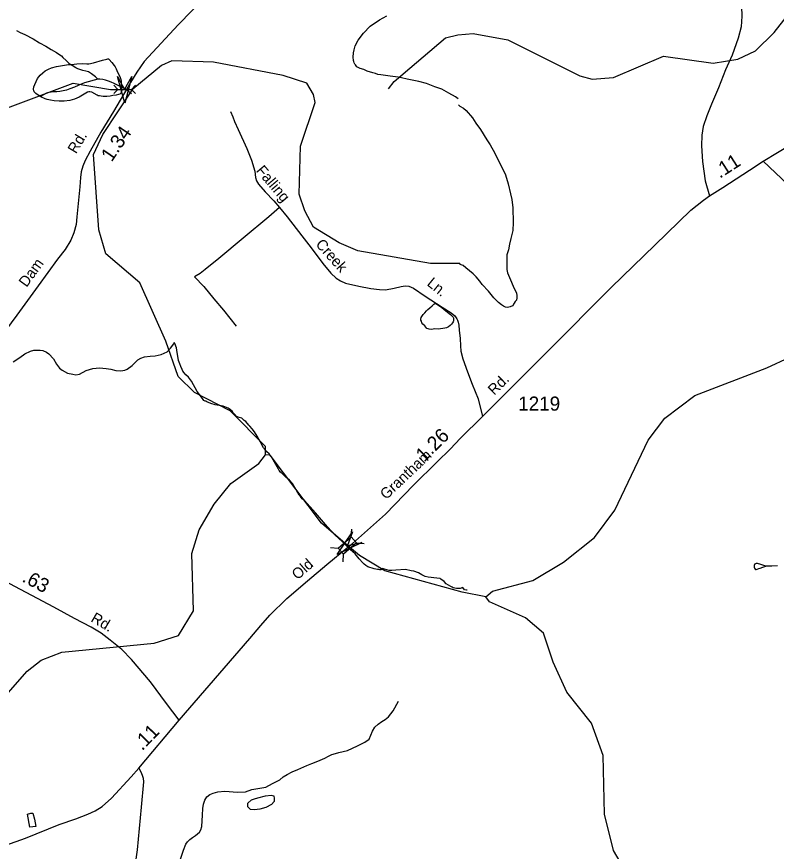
# Model space of a CAD drawing. Extents: x 2206922 to 2357709, y 510027 to 673830.
# Drawn here: x 2257136 to 2263859, y 570736 to 578126 of the extents above; entities that cross this region are included whole.
import ezdxf

# ---------------------------------------------------------------- set-up
doc = ezdxf.new("R2010")
doc.units = 0
for name, color, linetype in [('Exist Hydrographic Creek Single Shore', 7, 'Continuous'), ('Exist Hydrographic Misc Water Feature', 7, 'Continuous'), ('Exist Road Non-System Type 51', 7, 'Continuous'), ('Exist Road Non-System Type 51 Label', 7, 'Continuous'), ('Exist Road Secondary Mileage Hundredths English Label', 7, 'Continuous'), ('Exist Road Secondary Structure Pipe CELL', 7, 'Continuous'), ('Exist Road Secondary Structure Standard Bridge Attributed CELL', 7, 'Continuous'), ('Exist Road Secondary Structure Standard Bridge CELL', 7, 'Continuous'), ('Exist Road Secondary Type 51 Attributed', 7, 'Continuous'), ('Exist Road Secondary Type 51 Label', 7, 'Continuous'), ('Exist Road Secondary Type 51 Number Label', 7, 'Continuous')]:
    doc.layers.add(name, color=color, linetype=linetype)

msp = doc.modelspace()

# ---------------------------------------------------------------- linework, layer by layer
at = {"layer": 'Exist Hydrographic Creek Single Shore'}
for points in [[(2260540.9, 577584), (2260511, 577589.8), (2260442.7, 577599.2), (2260359.2, 577610.2), (2260333, 577614.1), (2260311.1, 577621.9), (2260287.3, 577629.6), (2260236.8, 577643.3), (2260208.9, 577657.2), (2260177, 577666.9), (2260146.4, 577682.5), (2260134.5, 577700.5), (2260128.1, 577706.3), (2260122.2, 577718.6), (2260118.3, 577728.5), (2260117.9, 577738.2), (2260114, 577766.4), (2260117.7, 577806.4), (2260123.2, 577832.3), (2260131, 577868.5), (2260156.9, 577918.5), (2260204.2, 577981.1), (2260265.5, 578043.3), (2260346.9, 578097.9), (2260413, 578134.6)], [(2261058.5, 575940.7), (2260798.5, 575941.1), (2260155.4, 576052.5), (2259988.5, 576124.8), (2259762.5, 576263.8), (2259686.5, 576406.4), (2259635.4, 576555), (2259648.5, 576981.1), (2259778.5, 577365.5), (2259761.5, 577437.9), (2259702.5, 577537.6), (2259493.5, 577604.1), (2258876.5, 577724.8), (2258509.5, 577735.5), (2258418.4, 577694.7), (2258163, 577484)], [(2261044.1, 577399.9), (2261018.5, 577416), (2260960.3, 577449.5), (2260899.8, 577485), (2260835.8, 577506.3), (2260763.4, 577533.9), (2260695.3, 577551), (2260591.4, 577572.4), (2260540.9, 577584)], [(2252747.3, 576540.1), (2252846.3, 576623.4), (2253510.3, 576937.9), (2253851.3, 576973.7), (2254770.3, 576682.9), (2255195.4, 576644.8), (2255603.5, 576662.8), (2256002.5, 576766.2), (2256359.5, 576913.1), (2257030.4, 577309.5), (2257636.4, 577536.7), (2257964.7, 577482.8), (2258091.2, 577482.8), (2258163, 577484)], [(2259337.5, 574245.5), (2259337.5, 574321.1), (2259026.4, 574635.6), (2258708.4, 574799.4), (2258565.4, 574940.1), (2258454.5, 575253.9), (2258225.5, 575770.1), (2257923.4, 576025.5), (2257863.3, 576239.9), (2257816.4, 576906.7), (2257898.4, 577082.1), (2258163, 577484)], [(2261044.7, 577344.3), (2261056.6, 577334.3), (2261089, 577316.5), (2261113.4, 577294.6), (2261170, 577229.3), (2261198.9, 577183.2), (2261241.6, 577127.6), (2261298.2, 577036.4), (2261326.7, 576990.7), (2261369.1, 576919), (2261461.2, 576726), (2261485.8, 576646.4), (2261506.9, 576556.4), (2261519, 576508.8), (2261525.8, 576432.7), (2261526.2, 576388.8), (2261530.7, 576346.8), (2261529.3, 576304.9), (2261525.8, 576232.8), (2261508.1, 576162.9), (2261496.9, 576110.6), (2261489.3, 576062.7), (2261473.9, 576018.4), (2261474.5, 575976.5), (2261474.9, 575922.6), (2261473.1, 575886.7), (2261481.3, 575856.7), (2261496.1, 575816.8), (2261514.1, 575775.1), (2261536.4, 575725.1), (2261558.8, 575681.6), (2261563.1, 575653.4), (2261563.1, 575635.5), (2261559.2, 575617.4), (2261547.5, 575605.4), (2261537.7, 575589.5), (2261531.7, 575579.4), (2261525.8, 575567.4), (2261510, 575561.2), (2261504, 575556.8), (2261492, 575555), (2261478, 575552.6), (2261462, 575554.6), (2261443.8, 575562.3), (2261425.9, 575574.3), (2261399.9, 575594), (2261359.5, 575635.8), (2261310.7, 575695.1), (2261256.6, 575754.7), (2261235.8, 575784.2), (2261203.4, 575821.9), (2261175.3, 575849.7), (2261142.7, 575875.7), (2261110.3, 575903.3), (2261088.2, 575923.2), (2261062.2, 575932.9), (2261058.5, 575940.7)], [(2261288.5, 572989.3), (2261079.6, 573029.6), (2260395.5, 573220.6), (2260170.3, 573354.4), (2260063.4, 573443.3), (2259833.5, 573641.9), (2259379.5, 574244.7), (2259337.5, 574245.5)], [(2262561.5, 570444.8), (2262535.5, 570543.7), (2262417.6, 570742.9), (2262339.4, 571066), (2262326.5, 571584.4), (2262223.6, 571871.8), (2262004.6, 572145.1), (2261884.4, 572409.9), (2261799.5, 572667.5), (2261639.6, 572801.9), (2261321.6, 572946), (2261288.5, 572989.3)]]:
    msp.add_lwpolyline(points, dxfattribs=at)
at = {"layer": 'Exist Hydrographic Misc Water Feature'}
for points in [[(2261041.5, 577966.3), (2261174.5, 577976.8), (2261483.5, 577921.4), (2262119.4, 577603.5), (2262228.5, 577571.7), (2262419.4, 577587.6), (2262859.4, 577775.5), (2263301.5, 577714), (2263517.5, 577749), (2263674.5, 577824.5), (2263840.6, 577985.2), (2264086.5, 578304.9), (2264260.6, 578449), (2264766.4, 578642), (2264998.5, 578804.6), (2265576.6, 579301.3), (2265965.6, 579539.4), (2266381.6, 579675.3), (2266780.7, 579736), (2266980.6, 579722.2), (2267497.5, 579626.5), (2268096.5, 579657)], [(2257133.4, 578004), (2257167.8, 577986.3)], [(2257167.8, 577986.3), (2257207.6, 577968.5), (2257282, 577929.4), (2257338, 577893.7), (2257392.5, 577866), (2257440.7, 577834.4), (2257488.9, 577808.9), (2257518.7, 577789), (2257531.2, 577779.5), (2257543.3, 577765.5), (2257573.4, 577737.8), (2257597.6, 577713.9), (2257611.7, 577704.1)], [(2260427.5, 577486.8), (2260476.5, 577551.4), (2260931.5, 577939.1), (2261041.5, 577966.3)], [(2257350.1, 577417.8), (2257325.7, 577432), (2257306, 577445.6), (2257291.7, 577459.5), (2257287.8, 577469.4), (2257285.7, 577485.5), (2257287.4, 577505.6), (2257294.9, 577525.5), (2257307, 577553.7), (2257321, 577579.6), (2257342.7, 577607.9), (2257366.3, 577629.9), (2257388.2, 577646.1), (2257416.1, 577662.6), (2257444, 577674.6), (2257487.7, 577685), (2257541.8, 577695.5), (2257593.9, 577701.8), (2257611.7, 577704.1)], [(2257611.7, 577704.1), (2257621.4, 577704.2), (2257667.7, 577708.6), (2257719.4, 577710.9), (2257757.5, 577709.2), (2257775.4, 577709.4), (2257815.4, 577717.5), (2257895.3, 577740.3), (2257933.1, 577750.5), (2257941.1, 577752.5), (2257947, 577752.9), (2257950.9, 577750.6), (2257955.4, 577746.7), (2257979.2, 577719.2), (2257999.5, 577693), (2258007.9, 577681.2), (2258017.5, 577663.5), (2258027.8, 577635.6), (2258038.3, 577613.4), (2258050.4, 577587.6), (2258058.6, 577569.7), (2258060.6, 577559.7), (2258060.8, 577539.8), (2258061, 577515.9), (2258063.3, 577501.7)], [(2257854.7, 577574.1), (2257832.6, 577593.7), (2257798.1, 577619.6), (2257772.3, 577637.3), (2257748.1, 577644.9), (2257721.9, 577650.9), (2257678.2, 577664.4), (2257657.7, 577674.4), (2257625.7, 577694.2), (2257611.7, 577704.1)], [(2257854.7, 577574.1), (2257737, 577541.2), (2257706.9, 577528.7), (2257679, 577516.7), (2257647.4, 577502.4), (2257607.2, 577486.1), (2257575.5, 577475.9), (2257545.7, 577469.4), (2257517.4, 577465.2), (2257491.8, 577461), (2257459.8, 577460.9), (2257441.6, 577458.8), (2257429.7, 577456.5), (2257399.9, 577448.5), (2257378, 577436.4), (2257362.2, 577428.2), (2257350.1, 577417.8)], [(2258063.3, 577501.7), (2258041.1, 577513.6), (2257998.9, 577533.3), (2257970.6, 577546.9), (2257948.9, 577556.7), (2257922.6, 577564.7), (2257896.8, 577570.3), (2257870.7, 577572.2), (2257854.7, 577574.1)], [(2258063.3, 577501.7), (2258065.1, 577473.9), (2258061.4, 577459.8), (2258057.3, 577447.9), (2258047.9, 577441.6), (2258037.8, 577437.4), (2258015.5, 577431.5), (2257987.6, 577427.2), (2257961.8, 577422.9), (2257933.9, 577420.7), (2257915.6, 577418.6), (2257899.8, 577420.5), (2257883.6, 577422.6), (2257867.7, 577424.2), (2257857.8, 577426.1), (2257847.8, 577430), (2257799.8, 577457.5), (2257781.7, 577461.5), (2257773.7, 577459.4), (2257763.5, 577457.3), (2257688, 577412.7), (2257646.2, 577396.3), (2257606.4, 577384.1), (2257556.4, 577377.8), (2257510.5, 577377.5), (2257468.6, 577380.9), (2257434.4, 577386.9), (2257405.9, 577392.4), (2257386.4, 577400.2), (2257350.1, 577417.8)], [(2258153.3, 577442.4), (2258123.4, 577468.3), (2258077.2, 577496), (2258063.3, 577501.7)], [(2261288.5, 572989.3), (2261346.6, 573040.7), (2261703.6, 573135.1), (2261976.5, 573296.8), (2262249.6, 573514.3), (2262430.5, 573756.6), (2262724.5, 574377.2), (2262872.6, 574570.9), (2263137.5, 574772.2), (2263776.4, 575018.4), (2264182.4, 575206.9), (2264612.6, 575519.6), (2265102.5, 575706.5), (2265933.6, 575939), (2266231.5, 576051), (2266422.6, 576152.1), (2266901.6, 576604.8), (2267215.6, 576808.4)], [(2260841.3, 575589.4), (2260845.2, 575587.2), (2260899.8, 575551.8), (2260933.8, 575521.9), (2260974, 575490.3), (2260994.1, 575472.7), (2260999.8, 575466.6), (2261002.5, 575458.9), (2261002.5, 575448.7), (2261002.3, 575432.9), (2260998.4, 575424.6), (2260992.4, 575416.6), (2260982.8, 575404.6), (2260972.6, 575392.4), (2260958.8, 575380.3), (2260939.1, 575372.3), (2260924.8, 575368.4), (2260869, 575359.7), (2260834.8, 575361.3), (2260810.8, 575357.2), (2260787, 575359.2), (2260776.9, 575361.1), (2260767.1, 575365), (2260748.8, 575388.8), (2260730.6, 575404.5), (2260723, 575416.6), (2260718.5, 575430.3), (2260714.2, 575438.6), (2260714.2, 575448.4), (2260716, 575462.3), (2260722.2, 575470.3), (2260734.1, 575488.4), (2260748.2, 575504.5), (2260762, 575520.7), (2260775.9, 575532.8), (2260791.3, 575549.1), (2260813.4, 575567.3), (2260827.4, 575579.4), (2260837.2, 575587.2), (2260841.3, 575589.4)], [(2257105.5, 575069.4), (2257162.9, 575107.8), (2257208.6, 575139.9), (2257258.4, 575164.4), (2257288.4, 575172.8), (2257318.5, 575174.8), (2257344.6, 575172.9), (2257368.1, 575169.3), (2257398.5, 575155.4), (2257420.6, 575142), (2257461, 575096.1), (2257489.1, 575050.5), (2257513.7, 575014.8), (2257539.6, 574996.7), (2257585.9, 574971.1), (2257632, 574959.6), (2257657.7, 574955.7), (2257691.9, 574961.9), (2257749.7, 574992.6), (2257809.4, 575011.2), (2257869.5, 575015.5), (2257927.7, 575012), (2257969.2, 575006.1), (2258013.7, 574994.5), (2258057.7, 574989.1), (2258091.6, 574995.4), (2258113.5, 575005.5), (2258156.8, 575037.9), (2258208.7, 575088.5), (2258234.3, 575102.4), (2258266.5, 575114.6), (2258316.5, 575120.9), (2258360.2, 575123.6), (2258414.1, 575135.7), (2258468, 575158.4), (2258498, 575192.4), (2258525.3, 575228.9), (2258529.4, 575240.8)], [(2259383, 574236.2), (2259370.7, 574254.3), (2259350.6, 574273.9), (2259328.7, 574299.6), (2259320.4, 574309.7), (2259294, 574357.5), (2259263.9, 574411.1), (2259241.1, 574451.1), (2259221.2, 574476.7), (2259199.3, 574500.3), (2259189, 574510.4), (2259163, 574540.3), (2259150.5, 574550.2), (2259138.6, 574562.2), (2259128.7, 574571.8), (2259104.3, 574575.9), (2259090.4, 574581.6), (2259078.5, 574589.5), (2259070.3, 574599.3), (2259052, 574619.5), (2259042, 574633.1), (2259027.8, 574645), (2259015.9, 574652.9), (2259007.5, 574659), (2258963.7, 574676.6), (2258893.7, 574689.9), (2258855.4, 574701.8), (2258819.3, 574715.4), (2258809.3, 574721.3), (2258803.1, 574723.1), (2258793.1, 574729.1), (2258779.1, 574744.9), (2258734.4, 574808.5), (2258681.7, 574900.3), (2258657.7, 574934), (2258633.7, 574955.8), (2258619.4, 574971.8), (2258605.2, 574987.3), (2258599.1, 575003.6), (2258589, 575027.5), (2258580.6, 575051.4), (2258568.5, 575083.2), (2258553.8, 575173.1), (2258549.9, 575192.7), (2258535.3, 575231), (2258529.4, 575240.8)], [(2256998.4, 572069.2), (2257229.5, 572330.2), (2257353.4, 572429.4), (2257536.5, 572497.8), (2258351.4, 572579.7), (2258567.5, 572647.5), (2258699.6, 572864.6), (2258686.4, 573373.2), (2258751.4, 573581.8), (2258883.5, 573808.7), (2259031.5, 573992.7), (2259279.4, 574171.3), (2259337.5, 574245.5)], [(2260374.4, 573238.8), (2260367, 573232.6), (2260358.6, 573228.6), (2260348.8, 573228.5), (2260340.8, 573230.5), (2260328.7, 573230.3), (2260314.5, 573234.5), (2260298.5, 573238.1), (2260244.6, 573255.5), (2260224.5, 573267.5), (2260212, 573277.5), (2260198.3, 573289.3), (2260165.9, 573327), (2260131.6, 573368.7), (2260089, 573406.3), (2260016.8, 573477.7), (2259954.5, 573535.3), (2259885.8, 573610.5), (2259781, 573731.8), (2259684, 573840.9), (2259663.7, 573856.5), (2259647.9, 573876.3), (2259635.8, 573890.3), (2259623.3, 573910.4), (2259597.5, 573956.1), (2259576.6, 573992.1), (2259548.9, 574021.8), (2259518.7, 574047.5), (2259492.3, 574075), (2259471.8, 574093), (2259459.7, 574107), (2259454.1, 574118.9), (2259417.6, 574180.7), (2259393, 574224.2), (2259383, 574236.2)], [(2261083.7, 573072.3), (2261059.7, 573064.1), (2261029.6, 573064.2), (2261013.8, 573066.2), (2260999.6, 573070), (2260989.6, 573075.9), (2260979.5, 573081.9), (2260937.5, 573105.3), (2260919, 573125.5), (2260889.1, 573147), (2260882.9, 573150.8), (2260855.1, 573154.6), (2260779, 573162), (2260750.9, 573169.9), (2260722.6, 573183.5), (2260692.5, 573201.4), (2260650.4, 573217.1), (2260628.5, 573220.8), (2260576.6, 573230.6), (2260492.5, 573223.9), (2260454.8, 573221.4), (2260432.7, 573221.1), (2260412.8, 573226.9), (2260392.5, 573232.8), (2260374.4, 573238.8)], [(2261121.8, 573048.7), (2261115.9, 573048.8), (2261099.5, 573050.4), (2261083.7, 573072.3)], [(2258586.6, 570667.6), (2258612, 570745.8), (2258631.3, 570798), (2258647.3, 570819.9), (2258668.8, 570840.1), (2258690.5, 570858.4), (2258718.6, 570876.4), (2258752.5, 570905), (2258766.2, 570926.9), (2258775.8, 570957), (2258781.2, 571054.8), (2258782.6, 571115), (2258790.2, 571153.1), (2258802.3, 571189.1), (2258819.7, 571217.3), (2258843.9, 571237.5), (2258873.4, 571251.7), (2258915.5, 571262), (2258977.4, 571268.5), (2259089.4, 571259.4), (2259161.1, 571261.9), (2259216.9, 571282.3), (2259250.9, 571290.5), (2259287, 571294.8), (2259341, 571305.3), (2259400.4, 571337.7), (2259464, 571368.3), (2259493.9, 571394.6), (2259530, 571416.8), (2259573.7, 571439.4), (2259623.7, 571461.4), (2259702.9, 571496.1), (2259749, 571512.7), (2259802.5, 571535.1), (2259864.5, 571559.4), (2259896.4, 571577.7), (2259926.4, 571591.8), (2259956.1, 571602.3), (2259986, 571610.4), (2260063.8, 571629.1), (2260153.6, 571669.9), (2260217.1, 571702.5), (2260256.7, 571728.5), (2260270.5, 571764.6), (2260284.2, 571798.6), (2260305.9, 571835.1), (2260333.8, 571861.3), (2260367.4, 571885.4), (2260397.8, 571903.6), (2260427.3, 571927.9), (2260466.7, 571980.4), (2260515.9, 572064.6)], [(2259182, 571162.2), (2259213.8, 571190.3), (2259241.9, 571200.7), (2259269.6, 571209), (2259337.3, 571227.2), (2259389.3, 571234), (2259411.5, 571226.2), (2259415.8, 571204.1), (2259413.7, 571178), (2259392, 571150), (2259342.2, 571123.5), (2259286.6, 571109.2), (2259240.5, 571102.8), (2259206.2, 571106.3), (2259182.2, 571130.2), (2259182, 571162.2)], [(2257279.8, 571074.7), (2257292.1, 571020.9), (2257305, 570954.9), (2257250.7, 570948.5), (2257229.9, 571064.4), (2257261.9, 571074.6), (2257279.8, 571074.7)]]:
    msp.add_lwpolyline(points, dxfattribs=at)
at = {"layer": 'Exist Road Non-System Type 51'}
for points in [[(2259027.4, 577287.9), (2259048.1, 577239.6), (2259063.6, 577198.2), (2259096.3, 577127.4), (2259173.7, 576959.3), (2259215.3, 576854.9), (2259244.6, 576758.3), (2259249.8, 576703.1), (2259258.4, 576673.8), (2259277.3, 576642.7), (2259336, 576575.5), (2259411.8, 576496.1), (2259462.6, 576435.2)], [(2259462.6, 576435.2), (2259368.7, 576354.7), (2259139.4, 576164.9), (2258925.7, 575985.5), (2258805, 575888.9), (2258758.4, 575852.7), (2258724, 575832), (2258708.4, 575823.4), (2258791.2, 575737.1), (2258880.8, 575628.5), (2258965.3, 575526.7), (2259079.1, 575387)], [(2259462.6, 576435.2), (2259529.6, 576354.7), (2259659.5, 576186.8), (2259742.2, 576079.8), (2259846.4, 575940.7), (2259915.4, 575854.8), (2259962.1, 575811.9), (2260001.2, 575786.6), (2260044.9, 575766.6), (2260163.7, 575739.8), (2260268.9, 575720), (2260347.8, 575710.8), (2260399.2, 575708.9), (2260476.3, 575723.6), (2260538.7, 575738.3), (2260575.1, 575744.4), (2260606.5, 575740.2), (2260646.9, 575723.6), (2260749.7, 575652), (2260902, 575552.9), (2260980.4, 575502.9), (2261012.6, 575476.1), (2261032.2, 575451.9), (2261038.2, 575438.5), (2261043.3, 575420.7), (2261047.9, 575393.6), (2261052.4, 575349.1), (2261061.6, 575277.5), (2261065.3, 575211.4), (2261067.1, 575163.7), (2261083.6, 575097.6), (2261125.8, 574981.9), (2261166.2, 574873.6), (2261221.2, 574741.4), (2261259.8, 574585.3)], [(2263767, 573259.9), (2263722.4, 573276.6), (2263693.2, 573284.9), (2263682, 573284.9), (2263675.1, 573282.2), (2263666.7, 573278), (2263665.3, 573273.8), (2263663.9, 573268.2), (2263663.9, 573261.3), (2263662.5, 573248.7), (2263665.3, 573241.8), (2263670.9, 573234.8), (2263675.1, 573232), (2263682, 573232), (2263690.4, 573233.4), (2263704.3, 573240.4), (2263715.4, 573244.5), (2263739.1, 573251.5), (2263767, 573259.9)], [(2263868.6, 573262.7), (2263818.5, 573259.9), (2263767, 573259.9)]]:
    msp.add_lwpolyline(points, dxfattribs=at)
at = {"layer": 'Exist Road Secondary Structure Pipe CELL'}
for p, q in [((2257995.9, 577519.7), (2258030.8, 577482.8)), ((2257995.9, 577446), (2258030.8, 577482.8)), ((2258030.8, 577482.8), (2258151.7, 577482.8)), ((2258186.6, 577519.7), (2258151.7, 577482.8)), ((2258186.6, 577446), (2258151.7, 577482.8))]:
    msp.add_line(p, q, dxfattribs=at)
at = {"layer": 'Exist Road Secondary Structure Standard Bridge Attributed CELL'}
for points in [[(2258154.1, 577596.6), (2258091.5, 577360.9), (2258027.9, 577596.3), (2258091.2, 577482.8)], [(2260190.6, 573469.9), (2259971.2, 573363.5), (2260108, 573565.4), (2260063.4, 573443.3)]]:
    msp.add_lwpolyline(points, close=True, dxfattribs=at)
at = {"layer": 'Exist Road Secondary Structure Standard Bridge CELL'}
for p, q in [((2260096, 573519.4), (2260100.6, 573588.3)), ((2259913.3, 573424.7), (2259982.1, 573420.1)), ((2260141.5, 573467.5), (2260210.3, 573462.9)), ((2260024, 573298.2), (2260028.6, 573367))]:
    msp.add_line(p, q, dxfattribs=at)
msp.add_lwpolyline([(2259982.1, 573420.1), (2260095.8, 573519.7), (2260142.3, 573466.6), (2260028.6, 573367)], close=True, dxfattribs=at)
at = {"layer": 'Exist Road Secondary Type 51 Attributed'}
for points in [[(2263392.7, 581682.7), (2263409.1, 581339), (2263441.1, 580593.6), (2263464.8, 580090.7), (2263485.7, 579636.5), (2263538.6, 578542.9), (2263548.4, 578307.4), (2263553.9, 578131.9), (2263548.4, 578037.1), (2263520.5, 577935.4), (2263469, 577786.4), (2263410.5, 577656.8), (2263346.5, 577495.2), (2263285.2, 577353.1), (2263243.4, 577248.6), (2263212.8, 577152.5), (2263198.9, 577075.8), (2263196.1, 576983.9), (2263205.8, 576843.2), (2263228.1, 576671.8), (2263268.5, 576540.9)], [(2259963.1, 579520.7), (2259703.1, 579222), (2259539.4, 579053.5), (2259320.6, 578834.4), (2258940.1, 578441.7), (2258564.6, 578054), (2258263.7, 577728.9), (2258198.7, 577634.9), (2258144.2, 577544)], [(2258144.2, 577544), (2258119.3, 577502.5), (2257991.7, 577285.7), (2257881, 577105.1), (2257787.2, 576936.5), (2257741.4, 576852.2), (2257719.8, 576801.7), (2257705.3, 576751.1), (2257700.5, 576702.9), (2257693.3, 576621), (2257678.8, 576471.7), (2257666.8, 576353.7), (2257662, 576286.3), (2257642.7, 576211.6), (2257616.3, 576146.6), (2257563.3, 576064.7), (2257498.3, 575980.4), (2257325, 575742), (2257137.3, 575484.3), (2256764.2, 574985.8), (2256434.4, 574540.2), (2256102.3, 574094.7), (2255904.9, 573824.9)], [(2263743.3, 576846), (2264123, 577078.6)], [(2263268.5, 576540.9), (2263385.7, 576614.1), (2263622.3, 576766.3), (2263743.3, 576846)], [(2263743.3, 576846), (2263961.9, 576639.8)], [(2260067.2, 573429.3), (2260107.5, 573462.7), (2260401, 573721.5), (2260646.9, 573978.6), (2260856.1, 574186), (2260973.5, 574298), (2261065.3, 574395.3), (2261259.8, 574585.3), (2261832.4, 575162.4), (2262399.6, 575731.4), (2262785.3, 576103.4), (2263101.4, 576412.7), (2263214.9, 576502.4), (2263268.5, 576540.9)], [(2258575.1, 571896), (2258462.7, 572044.4), (2258320.5, 572236.7), (2258151, 572433.2), (2258066.4, 572522.8), (2257963.7, 572606.3), (2257883.4, 572667.3), (2257795.2, 572721.9), (2257648.3, 572796.9), (2257464.6, 572898.5), (2257025.8, 573131.8), (2256604.5, 573348.1), (2256368.6, 573470.1), (2256318.9, 573495.8), (2256254.7, 573529.5), (2256192.1, 573572.9), (2256123.1, 573622.6), (2256065.3, 573667.6), (2255997.9, 573731.8), (2255951.4, 573772), (2255904.9, 573824.9)], [(2258575.1, 571896), (2259199, 572619.6), (2259296.1, 572734.4), (2259375.4, 572827), (2259528.1, 572974.2), (2259711.1, 573130.4), (2259881.8, 573275.4), (2260067.2, 573429.3)], [(2258215.6, 571472.8), (2258575.1, 571896)], [(2250467.3, 568916.3), (2250807.9, 569018.6), (2251107.1, 569099.2), (2251947.2, 569344.9), (2252586.5, 569525.3), (2254037, 569910.6), (2254393.3, 570013.3), (2255973.3, 570449.6), (2256015.6, 570461.3), (2256185.7, 570506.2), (2256293.2, 570536.3), (2256317.3, 570543.1), (2256670.2, 570659.9), (2256770.5, 570695.3), (2257212.7, 570851.4), (2257512.8, 570973.4), (2257660.4, 571023.2), (2257764.7, 571065), (2257830.5, 571095.5), (2257891.8, 571133.7), (2257974.9, 571207.9), (2258147.6, 571395.6), (2258215.6, 571472.8)], [(2258215.6, 571472.8), (2258235.3, 571439.1), (2258247.6, 571409.8), (2258254.1, 571382.8), (2258257.3, 571350.8), (2258238.1, 571127.6), (2258203.1, 570748.8), (2258155.4, 570417.1)]]:
    msp.add_lwpolyline(points, dxfattribs=at)

# ---------------------------------------------------------------- texts
at = {"layer": 'Exist Road Non-System Type 51 Label'}
for s, rotation, p in [('Falling', 310.23197, (2259249, 576760.5)), ('Creek', 311.75965, (2259775.7, 576106.9)), ('Ln.', 320.73689, (2260760.3, 575753.1))]:
    msp.add_text(s, height=95, rotation=rotation, dxfattribs=at).set_placement(p)
at = {"layer": 'Exist Road Secondary Mileage Hundredths English Label'}
for s, rotation, p in [('1.34', 55.66623, (2257976.1, 576834.2)), ('.11', 32.75249, (2263359.1, 576690.1)), ('1.26', 44.48002, (2260741.6, 574176.7)), ('.63', 331.75909, (2257175.7, 573128.5)), ('.11', 45.79439, (2258246.2, 571621.2))]:
    msp.add_text(s, height=125, rotation=rotation, dxfattribs=at).set_placement(p)
at = {"layer": 'Exist Road Secondary Type 51 Label'}
for s, rotation, p in [('Rd.', 58.93813, (2257661.2, 576906.2)), ('Dam', 54.23287, (2257222.9, 575724.5)), ('Rd.', 44.48002, (2261361.9, 574769.3)), ('Grantham', 43.39977, (2260406.1, 573844.8)), ('Old', 41.14463, (2259621.3, 573134.6)), ('Rd.', 329.55971, (2257784.9, 572775.3))]:
    msp.add_text(s, height=95, rotation=rotation, dxfattribs=at).set_placement(p)
at = {"layer": 'Exist Road Secondary Type 51 Number Label'}
msp.add_text('1219', height=125, dxfattribs=at).set_placement((2261574.1, 574637.7))

doc.saveas('drawing.dxf')
